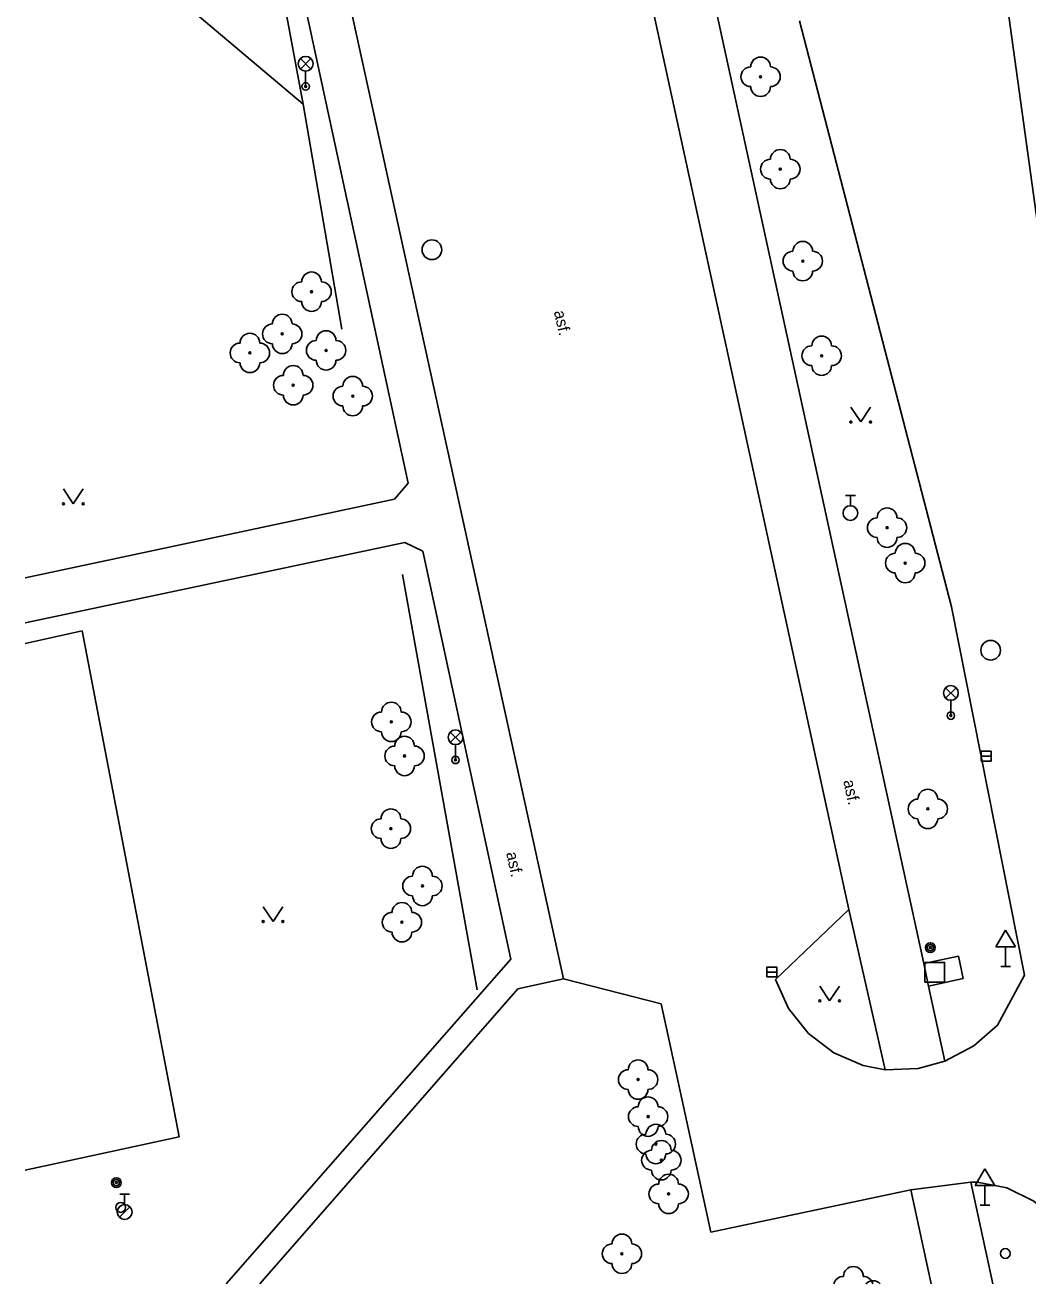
# Model space of a CAD drawing. Extents: x -640201 to -639641, y -1044739 to -1044317.
# Drawn here: x -640198.6 to -640147.6, y -1044733.6 to -1044669.7 of the extents above; entities that cross this region are included whole.
import ezdxf

# ---------------------------------------------------------------- set-up
doc = ezdxf.new("R2010")
doc.units = 0
for name, color, linetype in [('Ploty', 7, 'Continuous'), ('Popis povrchů', 7, 'Continuous'), ('Rozhraní ploch 1', 7, 'Continuous'), ('Sloupy_označník', 7, 'Continuous'), ('Zeleň - linie', 7, 'Continuous'), ('Zeleň - stromy', 7, 'Continuous'), ('Znaky doprava', 7, 'Continuous'), ('Znaky kanalizace', 7, 'Continuous'), ('Znaky voda', 7, 'Continuous'), ('Značky doprava', 7, 'Continuous'), ('Značky KM', 7, 'Continuous'), ('Šachty ner_', 7, 'Continuous')]:
    doc.layers.add(name, color=color, linetype=linetype)

msp = doc.modelspace()

# ---------------------------------------------------------------- linework, layer by layer
at = {"layer": 'Ploty'}
for p, q in [((-640184.43, -1044673.68), (-640182.47, -1044685.11)), ((-640179.4, -1044697.55), (-640175.6, -1044718.64)), ((-640198.551, -1044701.059), (-640195.65, -1044700.42)), ((-640195.65, -1044700.42), (-640190.73, -1044726.11)), ((-640190.73, -1044726.11), (-640198.551, -1044727.789))]:
    msp.add_line(p, q, dxfattribs=at)
at = {"layer": 'Rozhraní ploch 1'}
for p, q in [((-640168.34, -1044646.49), (-640152.929, -1044717.313)), ((-640170.36, -1044651.94), (-640156.73, -1044714.56)), ((-640179.108, -1044692.915), (-640187.15, -1044655.66)), ((-640184.99, -1044655.31), (-640171.216, -1044718.08)), ((-640146.1, -1044687.41), (-640148.79, -1044667.89)), ((-640151.52, -1044699.2), (-640159.23, -1044669.45)), ((-640179.8, -1044693.74), (-640179.108, -1044692.915)), ((-640179.8, -1044693.74), (-640198.551, -1044697.722)), ((-640179.28, -1044695.93), (-640198.551, -1044700.008)), ((-640178.36, -1044696.38), (-640179.28, -1044695.93)), ((-640173.89, -1044717.085), (-640178.36, -1044696.38)), ((-640151.52, -1044699.2), (-640147.81, -1044717.9)), ((-640156.73, -1044714.56), (-640160.46, -1044718.11)), ((-640154.88, -1044722.71), (-640156.73, -1044714.56)), ((-640188.338, -1044733.567), (-640173.89, -1044717.085)), ((-640152.929, -1044717.313), (-640151.17, -1044716.93)), ((-640150.922, -1044718.069), (-640151.17, -1044716.93)), ((-640171.216, -1044718.08), (-640173.54, -1044718.59)), ((-640171.216, -1044718.08), (-640166.26, -1044719.35)), ((-640152.681, -1044718.452), (-640150.922, -1044718.069)), ((-640147.81, -1044717.9), (-640149.18, -1044720.44)), ((-640186.63, -1044733.567), (-640173.54, -1044718.59)), ((-640166.26, -1044719.35), (-640163.74, -1044730.94)), ((-640153.59, -1044728.79), (-640150.54, -1044728.4)), ((-640149.417, -1044733.567), (-640150.54, -1044728.4)), ((-640163.74, -1044730.94), (-640153.59, -1044728.79)), ((-640153.59, -1044728.79), (-640152.556, -1044733.567))]:
    msp.add_line(p, q, dxfattribs=at)
for points in [[(-640152.929, -1044717.313), (-640152.681, -1044718.452), (-640151.85, -1044722.27)], [(-640160.46, -1044718.11), (-640159.793, -1044719.587), (-640158.786, -1044720.857), (-640157.5, -1044721.843), (-640156.011, -1044722.485), (-640154.88, -1044722.71)], [(-640151.85, -1044722.27), (-640150.376, -1044721.491), (-640149.18, -1044720.44)], [(-640154.88, -1044722.71), (-640153.212, -1044722.638), (-640151.85, -1044722.27)], [(-640144.84, -1044733.08), (-640145.338, -1044731.637), (-640146.191, -1044730.372), (-640147.343, -1044729.371), (-640148.715, -1044728.702), (-640150.214, -1044728.411), (-640150.54, -1044728.4)]]:
    msp.add_lwpolyline(points, dxfattribs=at)
at = {"layer": 'Sloupy_označník'}
for centre, radius in [((-640152.59, -1044716.5), 0.25), ((-640152.59, -1044716.5), 0.158), ((-640152.59, -1044716.5), 0.05), ((-640193.92, -1044728.43), 0.25), ((-640193.92, -1044728.43), 0.158), ((-640193.92, -1044728.43), 0.05)]:
    msp.add_circle(centre, radius, dxfattribs=at)
at = {"layer": 'Zeleň - linie'}
for p, q in [((-640184.43, -1044673.68), (-640186.04, -1044665.01)), ((-640191.33, -1044667.86), (-640184.43, -1044673.68))]:
    msp.add_line(p, q, dxfattribs=at)
at = {"layer": 'Zeleň - stromy'}
for centre in [(-640161.21, -1044672.29), (-640160.21, -1044676.98), (-640159.07, -1044681.65), (-640184.01, -1044683.2), (-640185.5, -1044685.34), (-640187.14, -1044686.31), (-640183.27, -1044686.18), (-640158.11, -1044686.45), (-640184.94, -1044687.95), (-640181.92, -1044688.5), (-640154.79, -1044695.18), (-640153.87, -1044696.98), (-640179.96, -1044705.04), (-640179.29, -1044706.77), (-640152.72, -1044709.46), (-640179.98, -1044710.46), (-640178.38, -1044713.37), (-640179.42, -1044715.21), (-640167.43, -1044723.2), (-640166.92, -1044725.08), (-640166.53, -1044726.47), (-640166.25, -1044727.29), (-640165.88, -1044729), (-640168.25, -1044732.04)]:
    msp.add_circle(centre, 0.05, dxfattribs=at)
for centre, start, end in [((-640161.71, -1044672.29), 90, 270), ((-640161.21, -1044671.79), 0, 180), ((-640160.71, -1044672.29), 270, 90), ((-640161.21, -1044672.79), 180, 0), ((-640160.21, -1044676.48), 0, 180), ((-640160.71, -1044676.98), 90, 270), ((-640159.71, -1044676.98), 270, 90), ((-640160.21, -1044677.48), 180, 0), ((-640159.07, -1044681.15), 0, 180), ((-640159.57, -1044681.65), 90, 270), ((-640158.57, -1044681.65), 270, 90), ((-640184.01, -1044682.7), 0, 180), ((-640159.07, -1044682.15), 180, 0), ((-640184.51, -1044683.2), 90, 270), ((-640183.51, -1044683.2), 270, 90), ((-640184.01, -1044683.7), 180, 0), ((-640185.5, -1044684.84), 0, 180), ((-640186, -1044685.34), 90, 270), ((-640185, -1044685.34), 270, 90), ((-640183.27, -1044685.68), 0, 180), ((-640187.64, -1044686.31), 90, 270), ((-640187.14, -1044685.81), 0, 180), ((-640186.64, -1044686.31), 270, 90), ((-640185.5, -1044685.84), 180, 0), ((-640183.77, -1044686.18), 90, 270), ((-640182.77, -1044686.18), 270, 90), ((-640158.11, -1044685.95), 0, 180), ((-640158.61, -1044686.45), 90, 270), ((-640157.61, -1044686.45), 270, 90), ((-640187.14, -1044686.81), 180, 0), ((-640184.94, -1044687.45), 0, 180), ((-640183.27, -1044686.68), 180, 0), ((-640158.11, -1044686.95), 180, 0), ((-640185.44, -1044687.95), 90, 270), ((-640184.44, -1044687.95), 270, 90), ((-640181.92, -1044688), 0, 180), ((-640182.42, -1044688.5), 90, 270), ((-640181.42, -1044688.5), 270, 90), ((-640184.94, -1044688.45), 180, 0), ((-640181.92, -1044689), 180, 0), ((-640155.29, -1044695.18), 90, 270), ((-640154.79, -1044694.68), 0, 180), ((-640154.29, -1044695.18), 270, 90), ((-640154.79, -1044695.68), 180, 0), ((-640153.87, -1044696.48), 0, 180), ((-640154.37, -1044696.98), 90, 270), ((-640153.37, -1044696.98), 270, 90), ((-640153.87, -1044697.48), 180, 0), ((-640179.96, -1044704.54), 0, 180), ((-640180.46, -1044705.04), 90, 270), ((-640179.46, -1044705.04), 270, 90), ((-640179.96, -1044705.54), 180, 0), ((-640179.79, -1044706.77), 90, 270), ((-640179.29, -1044706.27), 0, 180), ((-640178.79, -1044706.77), 270, 90), ((-640179.29, -1044707.27), 180, 0), ((-640152.72, -1044708.96), 0, 180), ((-640179.98, -1044709.96), 0, 180), ((-640153.22, -1044709.46), 90, 270), ((-640152.22, -1044709.46), 270, 90), ((-640180.48, -1044710.46), 90, 270), ((-640179.48, -1044710.46), 270, 90), ((-640152.72, -1044709.96), 180, 0), ((-640179.98, -1044710.96), 180, 0), ((-640178.38, -1044712.87), 0, 180), ((-640178.88, -1044713.37), 90, 270), ((-640177.88, -1044713.37), 270, 90), ((-640178.38, -1044713.87), 180, 0), ((-640179.42, -1044714.71), 0, 180), ((-640179.92, -1044715.21), 90, 270), ((-640178.92, -1044715.21), 270, 90), ((-640179.42, -1044715.71), 180, 0), ((-640167.43, -1044722.7), 0, 180), ((-640167.93, -1044723.2), 90, 270), ((-640166.93, -1044723.2), 270, 90), ((-640167.43, -1044723.7), 180, 0), ((-640166.92, -1044724.58), 0, 180), ((-640167.42, -1044725.08), 90, 270), ((-640166.42, -1044725.08), 270, 90), ((-640166.53, -1044725.97), 0, 180), ((-640167.03, -1044726.47), 90, 270), ((-640166.92, -1044725.58), 180, 0), ((-640166.03, -1044726.47), 270, 90), ((-640166.25, -1044726.79), 0, 180), ((-640166.75, -1044727.29), 90, 270), ((-640166.53, -1044726.97), 180, 0), ((-640165.75, -1044727.29), 270, 90), ((-640166.25, -1044727.79), 180, 0), ((-640165.88, -1044728.5), 0, 180), ((-640166.38, -1044729), 90, 270), ((-640165.38, -1044729), 270, 90), ((-640165.88, -1044729.5), 180, 0), ((-640168.25, -1044731.54), 0, 180), ((-640168.75, -1044732.04), 90, 270), ((-640167.75, -1044732.04), 270, 90), ((-640168.25, -1044732.54), 180, 0), ((-640156.5, -1044733.19), 0, 180), ((-640157, -1044733.69), 90, 165.76326), ((-640156, -1044733.69), 14.23674, 90), ((-640155.5, -1044733.91), 43.30871, 136.69129)]:
    msp.add_arc(centre, 0.5, start, end, dxfattribs=at)
at = {"layer": 'Znaky doprava'}
for p, q in [((-640184.575, -1044671.365), (-640184.045, -1044671.895)), ((-640184.575, -1044671.895), (-640184.045, -1044671.365)), ((-640184.31, -1044672.78), (-640184.31, -1044672.005)), ((-640151.815, -1044703.305), (-640151.285, -1044703.835)), ((-640151.815, -1044703.835), (-640151.285, -1044703.305)), ((-640151.55, -1044704.72), (-640151.55, -1044703.945)), ((-640176.965, -1044705.555), (-640176.435, -1044706.085)), ((-640176.965, -1044706.085), (-640176.435, -1044705.555)), ((-640176.7, -1044706.97), (-640176.7, -1044706.195))]:
    msp.add_line(p, q, dxfattribs=at)
for centre, radius in [((-640184.31, -1044671.63), 0.375), ((-640184.31, -1044672.78), 0.19), ((-640184.31, -1044672.78), 0.05), ((-640151.55, -1044703.57), 0.375), ((-640151.55, -1044704.72), 0.19), ((-640151.55, -1044704.72), 0.05), ((-640176.7, -1044705.82), 0.375), ((-640176.7, -1044706.97), 0.19), ((-640176.7, -1044706.97), 0.05)]:
    msp.add_circle(centre, radius, dxfattribs=at)
at = {"layer": 'Znaky kanalizace'}
for p, q in [((-640150.01, -1044706.78), (-640149.51, -1044706.78)), ((-640160.89, -1044717.74), (-640160.39, -1044717.74))]:
    msp.add_line(p, q, dxfattribs=at)
for points in [[(-640150.01, -1044707.03), (-640149.51, -1044707.03), (-640149.51, -1044706.53), (-640150.01, -1044706.53)], [(-640160.89, -1044717.99), (-640160.39, -1044717.99), (-640160.39, -1044717.49), (-640160.89, -1044717.49)]]:
    msp.add_lwpolyline(points, close=True, dxfattribs=at)
for centre in [(-640177.9, -1044681.07), (-640149.53, -1044701.4)]:
    msp.add_circle(centre, 0.5, dxfattribs=at)
at = {"layer": 'Znaky voda'}
for p, q in [((-640156.9, -1044693.54), (-640156.4, -1044693.54)), ((-640156.65, -1044694.065), (-640156.65, -1044693.54)), ((-640193.75, -1044729.02), (-640193.25, -1044729.02)), ((-640193.5, -1044729.545), (-640193.5, -1044729.02)), ((-640193.765, -1044730.185), (-640193.235, -1044729.655))]:
    msp.add_line(p, q, dxfattribs=at)
for centre, radius in [((-640156.65, -1044694.44), 0.375), ((-640193.7, -1044729.69), 0.25), ((-640193.5, -1044729.92), 0.375), ((-640148.786, -1044732.027), 0.25)]:
    msp.add_circle(centre, radius, dxfattribs=at)
at = {"layer": 'Značky doprava'}
for p, q in [((-640149.27, -1044716.46), (-640148.77, -1044715.61)), ((-640148.77, -1044715.61), (-640148.27, -1044716.46)), ((-640149.27, -1044716.46), (-640148.27, -1044716.46)), ((-640148.77, -1044717.46), (-640148.77, -1044716.46)), ((-640149.02, -1044717.46), (-640148.52, -1044717.46)), ((-640150.32, -1044728.58), (-640149.82, -1044727.73)), ((-640149.82, -1044727.73), (-640149.32, -1044728.58)), ((-640150.32, -1044728.58), (-640149.32, -1044728.58)), ((-640149.82, -1044729.58), (-640149.82, -1044728.58)), ((-640150.07, -1044729.58), (-640149.57, -1044729.58))]:
    msp.add_line(p, q, dxfattribs=at)
at = {"layer": 'Značky KM'}
for p, q in [((-640156.625, -1044689.065), (-640156.125, -1044689.815)), ((-640156.125, -1044689.815), (-640155.625, -1044689.065)), ((-640196.607, -1044693.216), (-640196.107, -1044693.966)), ((-640196.107, -1044693.966), (-640195.607, -1044693.216)), ((-640186.467, -1044714.424), (-640185.967, -1044715.174)), ((-640185.967, -1044715.174), (-640185.467, -1044714.424)), ((-640158.207, -1044718.452), (-640157.707, -1044719.202)), ((-640157.707, -1044719.202), (-640157.207, -1044718.452))]:
    msp.add_line(p, q, dxfattribs=at)
for centre in [(-640156.625, -1044689.815), (-640155.625, -1044689.815), (-640196.607, -1044693.966), (-640195.607, -1044693.966), (-640186.467, -1044715.174), (-640185.467, -1044715.174), (-640158.207, -1044719.202), (-640157.207, -1044719.202)]:
    msp.add_circle(centre, 0.05, dxfattribs=at)
at = {"layer": 'Šachty ner_'}
msp.add_lwpolyline([(-640152.87, -1044718.25), (-640151.87, -1044718.25), (-640151.87, -1044717.25), (-640152.87, -1044717.25)], close=True, dxfattribs=at)

# ---------------------------------------------------------------- texts
at = {"layer": 'Popis povrchů'}
for rotation, p in [(282.37659, (-640171.709, -1044684.212)), (282.27959, (-640157.021, -1044708.038)), (282.18261, (-640174.136, -1044711.698))]:
    msp.add_text('asf.', height=0.6, rotation=rotation, dxfattribs=at).set_placement(p)

doc.saveas('drawing.dxf')
